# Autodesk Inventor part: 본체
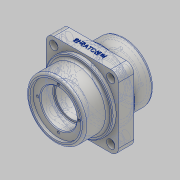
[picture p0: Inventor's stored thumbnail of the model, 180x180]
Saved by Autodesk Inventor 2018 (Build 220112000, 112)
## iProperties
Created: 2023-10
Part Number: 본체
Material: 알루미늄 6061
Document SubType Name: Modeling
Designer: home
Density: 2.7 g/cm^3
Appearance: 알루미늄 - 평지
Mass: 946.208 g
Surface Area: 537.857 cm^2
Volume: 350.447 cm^3
Author: home
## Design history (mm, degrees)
sketch "스케치1"
  geometry: L1 (37, -47)-(-37, -47); L2 (-47, -37)-(-47, 37); L3 (-37, 47)-(37, 47); L4 (47, 37)-(47, -37); L5 (47, -47)-(-47, 47); L6 (-47, -47)-(47, 47); C1 r 3.3 at (37, 37); C2 r 3.3 at (-37, 37); C3 r 3.3 at (-37, -37); C4 r 3.3 at (37, -37); A1 r 10 centre (37, -37) between (37, -47) and (47, -37); A2 r 10 centre (-37, -37) between (-47, -37) and (-37, -47); A3 r 10 centre (-37, 37) between (-37, 47) and (-47, 37); A4 r 10 centre (37, 37) between (47, 37) and (37, 47); 3 further points
  constraints: 12 end point, 8 centre point, 8 point on circle, 8 point on line, 8 tangent, 5 coincident, 3 equal radius, 3 midpoint, 2 parallel, 1 horizontal, 1 perpendicular
  dimensions: "d0" = 94 distance of L5.start L6.start; "d1" = 94 distance of L6.start L5.end; "d2" = 10 radius of A1; "d4" = 6.6 diameter of C1; "d5" = 6.6 diameter of C2; "d6" = 6.6 diameter of C3; "d7" = 6.6 diameter of C4
extrude "돌출1" new body sketch "스케치1" stored distance "d8" = 20; taper "d9" = 0 deg
sketch "스케치3"
  geometry: C1 r 3.3 at (-37, -37) reference; C2 r 5.5 at (-37, -37); C3 r 3.3 at (-37, 37) reference; C4 r 3.3 at (37, 37) reference; C5 r 3.3 at (37, -37) reference; C6 r 5.5 at (-37, 37); C7 r 5.5 at (37, 37); C8 r 5.5 at (37, -37); 1 further point
  constraints: 4 centre point, 4 coincident
  dimensions: "d16" = 11 diameter of C2; "d17" = 11 diameter of C6; "d18" = 11 diameter of C7; "d19" = 11 diameter of C8
extrude "돌출3" cut sketch "스케치3" distance "d20" = 7; taper "d21" = 0 deg
sketch "스케치4"
  geometry: C1 r 44 at (0, 0); 1 further point
  constraints: 1 centre point, 1 coincident
  dimensions: "d22" = 88 diameter of C1
extrude "돌출4" join sketch "스케치4" distance "d23" = 5; taper "d24" = 0 deg
sketch "스케치5"
  geometry: C1 r 38 at (0, 0); 1 further point
  constraints: 1 centre point, 1 coincident
  dimensions: "d25" = 76 diameter of C1
extrude "돌출5" join sketch "스케치5" distance "d26" = 30; taper "d27" = 0 deg
sketch "스케치6"
  geometry: L1 (0, -161.906)-(0, 161.906); L2 (-33, -45)-(-33, -41); L3 (-33, -41)-(-23.5, -41); L4 (-23.5, -41)-(-23.5, -24); L5 (-23.5, -24)-(-20.5, -24); L6 (-20.5, -24)-(-20.5, 24); L7 (-20.5, 24)-(-23.5, 24); L8 (-23.5, 24)-(-23.5, 41); L9 (-23.5, 41)-(-33, 41); L10 (-33, 41)-(-33, 45); L11 (-33, 45)-(0, 45); L12 (-33, -45)-(0, -45); L13 (0, -45)-(0, 45); 2 further points
  constraints: 26 end point, 8 perpendicular, 4 point on line, 2 vertical, 1 coincident, 1 collinear, 1 midpoint
  dimensions: "d39" = 66 diameter of L2 L1; "d40" = 47 diameter of L4 L1; "d41" = 47 diameter of L8 L1; "d42" = 41 diameter of L6 L1; "d43" = 45 distance from line of point (0, 0) L12; "d44" = 4 distance of L2.start L2.end; "d45" = 4 distance of L9.end L10.end; "d46" = 17 distance of L3.end L4.end; "d47" = 17 distance of L7.end L8.end; "d48" = 90 distance of L12.end L11.end; "d49" = 137.90625 distance from line of L1.end L7
revolve "회전1" sketch "스케치6" stored, may be unused: angle "d50" = 90 deg
sketch "스케치7"
  geometry: 2 further points
  constraints: 1 horizontal alignment
  dimensions: "d51" = 27 distance of point (0, 0) point (-27, 0)
hole "구멍1" sketch "스케치7" at (-27, 0) diameter "d52" = 3.242; stored, may be unused: countersink angle "d56" = 90 deg, drill point angle "d58" = 118 deg; dims "d53" = 8, "d54" = 4, "d55" = 2, "d57" = 10
sketch "스케치8"
  geometry: 2 further points
  constraints: 1 coincident
hole "구멍2" sketch "스케치8" at (-37, 10) diameter "d62" = 5.188; stored, may be unused: countersink angle "d66" = 90 deg, drill point angle "d68" = 118 deg; dims "d63" = 16, "d64" = 7, "d65" = 4, "d67" = 30
sketch "스케치9"
  geometry: C1 r 7 at (-37, 10); 1 further point
  constraints: 1 centre point, 1 coincident
  dimensions: "d69" = 14 diameter of C1
extrude "돌출6" cut sketch "스케치9" distance "d70" = 2; taper "d71" = 0 deg
fillet "모깎기1" dims "d72" = 3
fillet "모깎기3" dims "d74" = 1
sketch "스케치10"
  geometry: 2 further points
  constraints: 1 coincident, 1 other
feature "엠보싱1" sketch "스케치10" dims "d75" = 0.5, "d76" = 0
fillet "모깎기4" dims "d77" = 1
chamfer "모따기1" distance "d78" = 1; stored, may be unused: second distance "d79" = 2, angle "d80" = 45 deg
node "솔리드1"
mirror "미러1"
mirror "미러2"
pattern_circular "원형 패턴1" dims angle "d60" = 360 deg
mirror "미러3"
